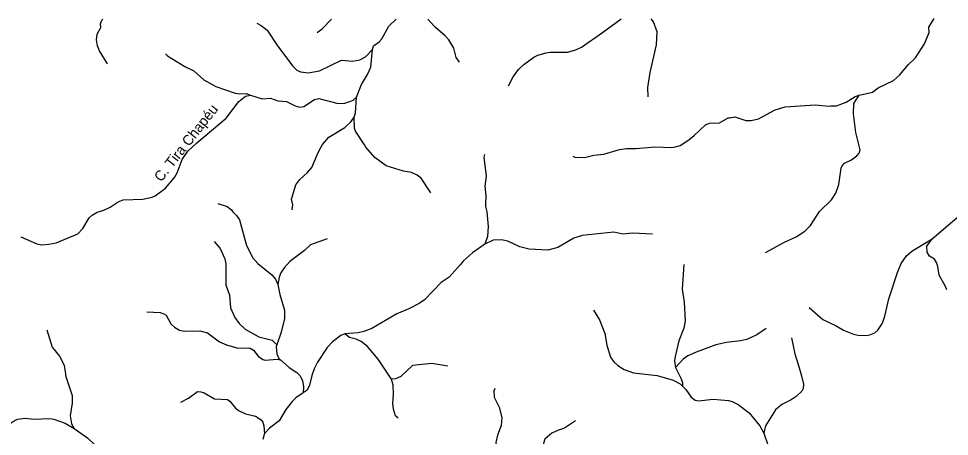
# Model space of a CAD drawing. Extents: x 473.9 to 500, y 7733.1 to 7760.8.
# Drawn here: x 487.72 to 494.97, y 7757.57 to 7760.82 of the extents above; entities that cross this region are included whole.
import ezdxf
from ezdxf.enums import TextEntityAlignment as Align

# ---------------------------------------------------------------- set-up
doc = ezdxf.new("R2010")
doc.units = 0
doc.header["$LTSCALE"] = 0.032
doc.layers.add('61', color=7, linetype='Continuous')
doc.layers.add('7', color=7, linetype='Continuous', lineweight=25)

msp = doc.modelspace()

# ---------------------------------------------------------------- linework, layer by layer
at = {"layer": '7'}
for points in [[(488.4171, 7760.4696), (488.3539, 7760.5695), (488.339, 7760.6092), (488.331, 7760.6552), (488.3365, 7760.7004), (488.3628, 7760.7522), (488.3614, 7760.7813), (488.371, 7760.8081), (488.3791, 7760.8162)], [(489.579, 7760.7869), (489.6135, 7760.7682), (489.6602, 7760.7303), (489.7353, 7760.6167), (489.858, 7760.4524), (489.8901, 7760.4208), (489.9195, 7760.4054), (489.9788, 7760.3976), (490.0666, 7760.4146), (490.2376, 7760.4962), (490.3252, 7760.4898), (490.3812, 7760.4993), (490.4248, 7760.5229), (490.48, 7760.5813)], [(490.0483, 7760.7142), (490.0889, 7760.7404), (490.1616, 7760.8176)], [(490.48, 7760.5813), (490.4885, 7760.6096), (490.5312, 7760.64), (490.5527, 7760.6628), (490.6072, 7760.7616), (490.6647, 7760.818)], [(491.1573, 7760.4827), (491.1322, 7760.5181), (491.1121, 7760.5903), (491.0739, 7760.6555), (491.0471, 7760.688), (490.9715, 7760.7508), (490.962, 7760.7587), (490.9109, 7760.8181)], [(491.5396, 7760.2983), (491.5751, 7760.3674), (491.6164, 7760.4238), (491.6594, 7760.4645), (491.7355, 7760.5207), (491.7676, 7760.5372), (491.8327, 7760.5539), (491.8643, 7760.5588), (491.9998, 7760.5588), (492.0638, 7760.577), (492.1075, 7760.5982), (492.2725, 7760.7125), (492.4175, 7760.8193)], [(492.6272, 7760.2117), (492.6253, 7760.2856), (492.6414, 7760.4015), (492.6909, 7760.6173), (492.6957, 7760.7183), (492.6684, 7760.7971), (492.65, 7760.8195)], [(494.269, 7760.226), (494.3729, 7760.2493), (494.4181, 7760.2829), (494.5376, 7760.3398), (494.5854, 7760.3805), (494.6543, 7760.4647), (494.7087, 7760.5152), (494.7798, 7760.624), (494.8157, 7760.7135), (494.8141, 7760.7548), (494.854, 7760.8211)], [(488.8667, 7760.546), (488.8823, 7760.53), (489.0178, 7760.4494), (489.0883, 7760.4141), (489.1669, 7760.345), (489.2587, 7760.2928), (489.4098, 7760.2413), (489.4474, 7760.2341), (489.4966, 7760.2388), (489.5308, 7760.2245)], [(490.3558, 7760.2087), (490.3945, 7760.3075), (490.4406, 7760.3853), (490.4656, 7760.4436), (490.48, 7760.5813)], [(487.7402, 7759.1204), (487.8668, 7759.0669), (487.9055, 7759.0602), (487.9592, 7759.0635), (488.016, 7759.076), (488.186, 7759.1446), (488.2229, 7759.1851), (488.2743, 7759.2684), (488.2953, 7759.2908), (488.3354, 7759.3127), (488.3865, 7759.3284), (488.4354, 7759.3515), (488.4995, 7759.3943), (488.5391, 7759.4088), (488.6917, 7759.4139), (488.7276, 7759.4222), (488.7632, 7759.4305), (488.7882, 7759.442), (488.8685, 7759.5016), (488.937, 7759.5826), (488.9581, 7759.6205), (488.9972, 7759.7241), (489.0424, 7759.7877), (489.1108, 7759.8545), (489.3393, 7760.047), (489.4401, 7760.1758), (489.4911, 7760.2159), (489.5308, 7760.2245)], [(489.5308, 7760.2245), (489.6198, 7760.1964), (489.6848, 7760.2003), (489.7433, 7760.1804), (489.8106, 7760.1747), (489.8786, 7760.1425), (489.9147, 7760.1322), (489.9445, 7760.1355), (490.0277, 7760.1917), (490.061, 7760.2002), (490.2131, 7760.1604), (490.2652, 7760.1635), (490.3039, 7760.1749), (490.3284, 7760.1861), (490.3558, 7760.2087)], [(490.338, 7760.053), (490.3469, 7760.086), (490.3558, 7760.2087)], [(492.04, 7759.7485), (492.057, 7759.7408), (492.1313, 7759.7401), (492.2032, 7759.7569), (492.2826, 7759.7655), (492.4039, 7759.8018), (492.4594, 7759.8106), (492.5333, 7759.8107), (492.6789, 7759.8228), (492.8102, 7759.818), (492.8381, 7759.8216), (492.8763, 7759.8336), (492.9424, 7759.876), (492.9856, 7759.9097), (493.0729, 7759.9944), (493.1037, 7760.0056), (493.1813, 7760.0103), (493.2493, 7760.0472), (493.2608, 7760.0491), (493.3014, 7760.056), (493.3866, 7760.0288), (493.4291, 7760.0278), (493.4857, 7760.0405), (493.6152, 7760.11), (493.6948, 7760.1338), (493.9265, 7760.1507), (494.0341, 7760.1403), (494.0496, 7760.1407), (494.0938, 7760.1419), (494.1691, 7760.1705), (494.239, 7760.2146), (494.269, 7760.226)], [(493.5414, 7759), (493.6879, 7759.0812), (493.7785, 7759.1213), (493.8465, 7759.1651), (493.8912, 7759.2095), (493.9618, 7759.3191), (494.0553, 7759.4103), (494.0877, 7759.4628), (494.1093, 7759.522), (494.1106, 7759.5301), (494.1301, 7759.6564), (494.1387, 7759.6753), (494.1556, 7759.6942), (494.2105, 7759.7222), (494.2518, 7759.7512), (494.2697, 7759.7733), (494.2769, 7759.7994), (494.2434, 7759.9335), (494.2256, 7760.0797), (494.23, 7760.1612), (494.269, 7760.226)], [(489.8529, 7759.3329), (489.859, 7759.37), (489.8487, 7759.4152), (489.8819, 7759.5259), (489.9133, 7759.5674), (489.9749, 7759.6217), (490.0081, 7759.6605), (490.0478, 7759.7599), (490.0657, 7759.7943), (490.0898, 7759.8403), (490.1408, 7759.8966), (490.2645, 7759.9738), (490.3133, 7760.0186), (490.338, 7760.053)], [(490.9352, 7759.4646), (490.8597, 7759.5789), (490.8282, 7759.6019), (490.7844, 7759.6227), (490.7218, 7759.6342), (490.5869, 7759.6753), (490.4986, 7759.7389), (490.4289, 7759.8211), (490.4185, 7759.8368), (490.3472, 7759.944), (490.3386, 7759.969), (490.338, 7760.053)], [(491.3509, 7759.7637), (491.3481, 7759.7413), (491.3656, 7759.5942), (491.3553, 7759.5159), (491.3617, 7759.4398), (491.3605, 7759.3762), (491.3601, 7759.3568), (491.3696, 7759.3168), (491.3809, 7759.2025), (491.3744, 7759.1244), (491.3548, 7759.0644)], [(494.8378, 7759.1062), (495.1424, 7759.3648), (495.3719, 7759.5015), (495.4409, 7759.5275), (495.4657, 7759.5369), (495.6506, 7759.5914), (495.7372, 7759.6314), (495.884, 7759.6688), (496.0277, 7759.6912), (496.2714, 7759.6768), (496.5005, 7759.6274), (496.6633, 7759.6207), (496.7229, 7759.6338)], [(489.2761, 7759.3823), (489.3489, 7759.3586), (489.3826, 7759.3326), (489.3894, 7759.3177), (489.4207, 7759.2885), (489.4448, 7759.2536), (489.498, 7759.0529), (489.5485, 7758.9588), (489.5869, 7758.9139), (489.6946, 7758.8255), (489.7232, 7758.7913), (489.7434, 7758.7501)], [(490.1276, 7759.1056), (489.9971, 7759.0602), (489.9491, 7759.0156), (489.8355, 7758.9292), (489.7915, 7758.8796), (489.7667, 7758.8404), (489.752, 7758.8066), (489.7434, 7758.7501)], [(492.6594, 7759.143), (492.5054, 7759.1509), (492.4306, 7759.1429), (492.3587, 7759.158), (492.1131, 7759.1314), (492.0477, 7759.1114), (491.9223, 7759.0379), (491.8446, 7759.017), (491.6993, 7759.0266), (491.6284, 7759.0447), (491.5339, 7759.0872), (491.4854, 7759.0987), (491.4193, 7759.0958), (491.3548, 7759.0644)], [(493.8807, 7758.5703), (493.9885, 7758.4766), (494.0909, 7758.4284), (494.1489, 7758.3938), (494.2261, 7758.3638), (494.2612, 7758.3554), (494.3257, 7758.3523), (494.3545, 7758.3572), (494.3928, 7758.375), (494.4169, 7758.3936), (494.451, 7758.4479), (494.4711, 7758.5044), (494.502, 7758.6378), (494.5693, 7758.8447), (494.5978, 7758.913), (494.6396, 7758.9723), (494.6813, 7759.0107), (494.8378, 7759.1062)], [(494.952, 7758.7094), (494.9435, 7758.7345), (494.8921, 7758.8239), (494.8831, 7758.8915), (494.8734, 7758.9207), (494.8558, 7758.9469), (494.8183, 7758.9704), (494.7987, 7759.0015), (494.7981, 7759.0479), (494.8378, 7759.1062)], [(489.247, 7759.0847), (489.2932, 7759.0318), (489.3303, 7758.9507), (489.3387, 7758.9113), (489.338, 7758.7466), (489.3651, 7758.666), (489.3733, 7758.5692), (489.4079, 7758.4936), (489.4403, 7758.4463), (489.4885, 7758.4033), (489.5939, 7758.3429), (489.6987, 7758.3169), (489.7342, 7758.2791)], [(491.3548, 7759.0644), (491.2587, 7758.998), (491.189, 7758.9341), (491.1624, 7758.9041), (491.0773, 7758.808), (491.0159, 7758.7658), (490.8843, 7758.6303), (490.8429, 7758.6029), (490.7624, 7758.5599), (490.669, 7758.523), (490.4756, 7758.4079), (490.4133, 7758.3833), (490.3686, 7758.3727), (490.2655, 7758.3652)], [(492.9034, 7758.9062), (492.8907, 7758.7143), (492.9083, 7758.6137), (492.9138, 7758.4685), (492.9035, 7758.4094), (492.8664, 7758.311), (492.8362, 7758.1882), (492.833, 7758.1546), (492.8398, 7758.1031)], [(489.7434, 7758.7501), (489.7581, 7758.6734), (489.795, 7758.5495), (489.7949, 7758.4858), (489.7685, 7758.378), (489.7342, 7758.2791)], [(488.7233, 7758.5384), (488.8258, 7758.5311), (488.8556, 7758.5228), (488.8729, 7758.5102), (488.9088, 7758.4437), (488.9366, 7758.418), (488.9777, 7758.3937), (489.0162, 7758.386), (489.1362, 7758.3883), (489.1939, 7758.3745), (489.2895, 7758.3046), (489.343, 7758.2791), (489.4239, 7758.2577), (489.5271, 7758.2544), (489.552, 7758.2391), (489.5898, 7758.1908), (489.6248, 7758.1651), (489.644, 7758.1606), (489.738, 7758.1687), (489.7644, 7758.1626)], [(492.2012, 7758.5502), (492.2472, 7758.4743), (492.2882, 7758.3696), (492.3061, 7758.2776), (492.3335, 7758.1844), (492.3587, 7758.148), (492.3906, 7758.1185), (492.4411, 7758.0875), (492.5127, 7758.0629), (492.6977, 7758.0403), (492.8227, 7758.0057), (492.8763, 7757.9778), (492.895, 7757.9591)], [(487.9432, 7758.3959), (487.9847, 7758.2614), (488.042, 7758.1913), (488.0784, 7758.1231), (488.0904, 7758.0336), (488.1402, 7757.8869), (488.14, 7757.8251), (488.1241, 7757.7281), (488.1366, 7757.6642), (488.1564, 7757.6295)], [(490.2655, 7758.3652), (490.2342, 7758.3537), (490.1683, 7758.3046), (490.1256, 7758.2594), (490.0527, 7758.1452), (490.0263, 7758.0926), (490.0069, 7758.0426), (489.9882, 7757.9653), (489.9701, 7757.9272), (489.9387, 7757.906)], [(490.6282, 7758.0119), (490.5227, 7758.1689), (490.4417, 7758.2666), (490.3903, 7758.3059), (490.3521, 7758.3239), (490.3014, 7758.3381), (490.2655, 7758.3652)], [(493.5464, 7758.4072), (493.473, 7758.3592), (493.3944, 7758.3229), (493.3473, 7758.3111), (493.2359, 7758.2993), (493.1532, 7758.2796), (493.0507, 7758.2422), (493.0001, 7758.2238), (492.9364, 7758.195), (492.8984, 7758.1691), (492.8398, 7758.1031)], [(493.7435, 7758.3353), (493.7687, 7758.2097), (493.7967, 7758.1191), (493.8215, 7758.0387), (493.836, 7757.974), (493.8336, 7757.9412), (493.824, 7757.9186), (493.7803, 7757.8779), (493.7413, 7757.8519), (493.667, 7757.8155), (493.6191, 7757.773), (493.54, 7757.6489), (493.5277, 7757.5933)], [(489.7342, 7758.2791), (489.7289, 7758.2638), (489.735, 7758.2096), (489.7516, 7758.1741), (489.7644, 7758.1626)], [(489.7644, 7758.1626), (489.8297, 7758.1043), (489.8893, 7758.0646), (489.9168, 7758.0387), (489.9358, 7758.0009), (489.9425, 7757.955), (489.9387, 7757.906)], [(491.0659, 7758.1143), (490.9426, 7758.1342), (490.7916, 7758.1188), (490.6995, 7758.0349), (490.6583, 7758.0165), (490.6282, 7758.0119)], [(492.8398, 7758.1031), (492.8813, 7758.0205), (492.893, 7757.9874), (492.895, 7757.9591)], [(490.6788, 7757.7095), (490.6598, 7757.7272), (490.6434, 7757.7799), (490.6376, 7757.8234), (490.6433, 7757.8945), (490.6409, 7757.9663), (490.6282, 7758.0119)], [(491.4328, 7757.94), (491.4295, 7757.9331), (491.4258, 7757.9254), (491.4287, 7757.8729), (491.4673, 7757.7937), (491.4875, 7757.7148), (491.481, 7757.6524), (491.4525, 7757.576), (491.4403, 7757.5199), (491.4523, 7757.4291), (491.4689, 7757.388), (491.5408, 7757.286), (491.5737, 7757.1962), (491.6292, 7757.1362), (491.653, 7757.1032), (491.6721, 7757.0618)], [(492.895, 7757.9591), (492.9204, 7757.9337), (492.963, 7757.8717), (492.9927, 7757.8487), (493.0189, 7757.8448), (493.1338, 7757.8575), (493.2535, 7757.8464), (493.2824, 7757.8392), (493.3267, 7757.8162), (493.4123, 7757.7511), (493.481, 7757.6672), (493.4964, 7757.6484), (493.5277, 7757.5933)], [(488.9878, 7757.8332), (489.0471, 7757.866), (489.1178, 7757.9168), (489.1437, 7757.9154), (489.1682, 7757.9055), (489.2504, 7757.8609), (489.3497, 7757.8539), (489.3692, 7757.8423), (489.4131, 7757.7873), (489.4427, 7757.765), (489.4905, 7757.7436), (489.5679, 7757.7258), (489.6121, 7757.6971), (489.6254, 7757.6786), (489.6328, 7757.6497), (489.6379, 7757.5896)], [(489.9387, 7757.906), (489.8837, 7757.8679), (489.8552, 7757.8402), (489.8039, 7757.776), (489.7531, 7757.6884), (489.6765, 7757.6309), (489.6379, 7757.5896)], [(487.3193, 7757.6394), (487.4027, 7757.6386), (487.4861, 7757.6114), (487.5378, 7757.6107), (487.5838, 7757.6239), (487.62, 7757.642), (487.6884, 7757.689), (487.7143, 7757.7004), (487.7772, 7757.7093), (487.8428, 7757.7021), (487.9615, 7757.7069), (487.9849, 7757.7034), (487.9986, 7757.7013), (488.0871, 7757.67), (488.1564, 7757.6295)], [(492.0601, 7757.6892), (491.9761, 7757.6316), (491.9275, 7757.6161), (491.8778, 7757.5911), (491.8233, 7757.5454), (491.8107, 7757.5127), (491.8042, 7757.4537), (491.8074, 7757.3614), (491.7987, 7757.3142), (491.7819, 7757.2829), (491.7129, 7757.1992), (491.6721, 7757.0618)], [(488.1564, 7757.6295), (488.2076, 7757.5922), (488.2622, 7757.5526), (488.3649, 7757.4568), (488.4241, 7757.4387), (488.5069, 7757.435), (488.5451, 7757.4161), (488.6674, 7757.3261), (488.7063, 7757.3039)], [(489.6379, 7757.5896), (489.636, 7757.5825), (489.6251, 7757.5419)], [(493.5277, 7757.5933), (493.561, 7757.4945), (493.5804, 7757.4738), (493.6057, 7757.4629), (493.6698, 7757.4565), (493.7198, 7757.4394), (493.7579, 7757.4112), (493.8247, 7757.3032), (493.8904, 7757.2251), (494.0045, 7757.126), (494.0454, 7757.097), (494.1642, 7757.0356), (494.2971, 7756.9448), (494.3878, 7756.8727), (494.468, 7756.7805), (494.5012, 7756.756), (494.5515, 7756.7299), (494.7189, 7756.6664), (494.7582, 7756.645), (494.7736, 7756.632), (494.7854, 7756.6081), (494.8159, 7756.5705), (494.8609, 7756.5353), (495.0451, 7756.4561)]]:
    msp.add_lwpolyline(points, dxfattribs=at)

# ---------------------------------------------------------------- texts
at = {"layer": '61'}
msp.add_text('C. Tira Chapéu', height=0.08, rotation=51.884, dxfattribs=at).set_placement((489.0588, 7759.8291), align=Align.CENTER)

doc.saveas('drawing.dxf')
